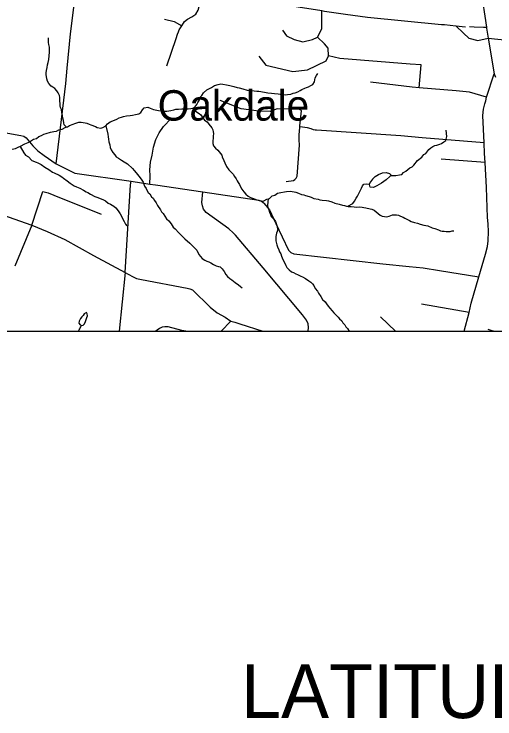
# Model space of a CAD drawing. Extents: x 0 to 69.5, y -4.5 to 22.
# Drawn here: x 2.482 to 3.731, y 13.194 to 15.023 of the extents above; entities that cross this region are included whole.
import ezdxf

# ---------------------------------------------------------------- set-up
doc = ezdxf.new("R2010")
doc.units = 0
for name, color, linetype in [('GM_X_County_Road', 7, 'Continuous'), ('GM_X_County_ROW', 7, 'Continuous'), ('GM_X_Minor_Lake', 7, 'Continuous'), ('GM_X_Minor_River', 7, 'Continuous'), ('GM_X_Township_Subdivision', 7, 'Continuous'), ('GM_X_Unincorporated_Text', 7, 'Continuous'), ('SH_Data', 7, 'Continuous')]:
    doc.layers.add(name, color=color, linetype=linetype)

msp = doc.modelspace()

# ---------------------------------------------------------------- linework, layer by layer
at = {"layer": 'GM_X_County_Road'}
for points in [[(2.2258, 15.2235), (2.2987, 15.186), (2.3184, 15.1766), (2.3423, 15.1693), (2.373, 15.1638), (2.4076, 15.1648), (2.4442, 15.1636), (2.6483, 15.131), (2.7856, 15.1056), (2.9731, 15.0809), (3.1585, 15.0511), (3.281, 15.0319), (3.2884, 15.0308), (3.343, 15.0226), (3.3998, 15.0151), (3.5922, 14.9963), (3.5999, 14.9956)], [(2.6198, 14.8825), (2.6281, 14.9717), (2.6483, 15.131)], [(3.6945, 15.0867), (3.7086, 14.9889), (3.7089, 14.9865), (3.7134, 14.9601), (3.7288, 14.8681), (3.7325, 14.8589)], [(3.5999, 14.9956), (3.6295, 14.9929), (3.6491, 14.9734), (3.6629, 14.9607), (3.686, 14.9547), (3.7134, 14.9601)], [(3.6295, 14.9929), (3.6543, 14.9903)], [(3.6768, 14.9901), (3.7006, 14.9892)], [(3.7134, 14.9601), (3.8399, 14.9472), (3.85, 14.9435), (3.9106, 14.9291), (3.9265, 14.9232), (3.9472, 14.9185), (4.0106, 14.9118), (4.0583, 14.9068)], [(3.7129, 14.4789), (3.7118, 14.495), (3.7085, 14.5729), (3.7053, 14.6379), (3.7039, 14.6616), (3.7029, 14.6892), (3.699, 14.7598), (3.7006, 14.7761), (3.7047, 14.7898), (3.7068, 14.7981), (3.7092, 14.807), (3.7288, 14.8681)], [(2.3393, 14.7315), (2.4266, 14.7207), (2.4996, 14.7079), (2.5073, 14.7062), (2.5134, 14.7016), (2.5301, 14.6807), (2.5431, 14.6681), (2.5604, 14.6558), (2.5911, 14.634), (2.6279, 14.6158), (2.6392, 14.6102), (2.7855, 14.589), (2.8343, 14.5818), (2.8491, 14.5796)], [(2.7703, 14.3525), (2.7846, 14.5795), (2.7846, 14.5795)], [(2.7846, 14.5795), (2.7855, 14.589)], [(2.8491, 14.5796), (2.9723, 14.5615), (3.1178, 14.5405), (3.1238, 14.5388), (3.129, 14.5343)], [(2, 14.5396), (2.019, 14.5376), (2.0727, 14.5308), (2.2375, 14.5181), (2.273, 14.5212), (2.3066, 14.52), (2.3558, 14.5219), (2.3858, 14.5244), (2.3884, 14.5247), (2.3912, 14.5244), (2.4003, 14.5218), (2.4213, 14.5128), (2.5283, 14.475), (2.5681, 14.4589), (2.6134, 14.4384), (2.6877, 14.3965), (2.7703, 14.3525)], [(3.129, 14.5343), (3.1309, 14.5326), (3.1449, 14.5152), (3.1617, 14.4795), (3.1943, 14.4106), (3.2005, 14.404), (3.2088, 14.4008), (3.4396, 14.3745), (3.5082, 14.3678), (3.5441, 14.3643), (3.5868, 14.3576), (3.6892, 14.3408)], [(3.6512, 14.2), (3.6635, 14.249), (3.6693, 14.2725), (3.6892, 14.3408), (3.7063, 14.3997), (3.7111, 14.4197), (3.7131, 14.4349), (3.714, 14.4585), (3.7129, 14.4777), (3.7129, 14.4789)], [(2.7703, 14.3525), (2.7763, 14.3485), (2.7925, 14.34), (2.7996, 14.3369), (2.8125, 14.3338), (2.9315, 14.3114), (2.9387, 14.3101), (2.9454, 14.3072), (2.9907, 14.2625), (3.0097, 14.2478), (3.0297, 14.2365), (3.0449, 14.2264), (3.0549, 14.2233), (3.0685, 14.2188), (3.1275, 14.2)]]:
    msp.add_lwpolyline(points, dxfattribs=at)
at = {"layer": 'GM_X_County_ROW'}
for points in [[(3.6649, 14.9905), (3.6768, 14.9901)], [(3.7006, 14.9892), (3.7086, 14.9889)], [(2.5911, 14.634), (2.6162, 14.8432), (2.6198, 14.8825)]]:
    msp.add_lwpolyline(points, dxfattribs=at)
at = {"layer": 'GM_X_Minor_Lake'}
for points in [[(2.657, 14.2147), (2.6612, 14.2158), (2.665, 14.2195), (2.6674, 14.2248), (2.6691, 14.2308), (2.6711, 14.2357), (2.6723, 14.2402), (2.6717, 14.2448), (2.6702, 14.2483), (2.6641, 14.245), (2.661, 14.2412), (2.6575, 14.2371), (2.6543, 14.233), (2.6508, 14.2259), (2.6499, 14.2206)], [(2.6499, 14.2206), (2.6538, 14.2165), (2.657, 14.2147)]]:
    msp.add_lwpolyline(points, dxfattribs=at)
at = {"layer": 'GM_X_Minor_River'}
for points in [[(2.6176, 14.7296), (2.6118, 14.7354), (2.6108, 14.7411), (2.6098, 14.7472), (2.6088, 14.7526), (2.6075, 14.7598), (2.6062, 14.7679), (2.6049, 14.7751), (2.6027, 14.7802), (2.6017, 14.7848), (2.6011, 14.7897), (2.6006, 14.7981), (2.6004, 14.8065), (2.5994, 14.8119), (2.5965, 14.8184), (2.5925, 14.8239), (2.5873, 14.8297), (2.5829, 14.8336), (2.578, 14.8361), (2.5721, 14.8427), (2.5685, 14.8493), (2.5671, 14.8546), (2.5657, 14.8608), (2.5655, 14.8654), (2.5653, 14.8707), (2.5662, 14.8764), (2.5675, 14.8843), (2.5689, 14.8915), (2.5705, 14.8976), (2.5719, 14.9055), (2.5733, 14.915), (2.5739, 14.9245), (2.5741, 14.9321), (2.5735, 14.9375), (2.5722, 14.944), (2.5716, 14.9493), (2.5714, 14.9562), (2.5711, 14.9615)], [(3.1411, 14.8188), (3.1502, 14.8178), (3.1586, 14.8168), (3.1681, 14.8161), (3.173, 14.8156), (3.1821, 14.8142), (3.1878, 14.8137), (3.1923, 14.8139), (3.2007, 14.8152), (3.2065, 14.8174), (3.2115, 14.8187), (3.2184, 14.8216), (3.2246, 14.8245), (3.2292, 14.827), (3.2369, 14.831), (3.2415, 14.8324), (3.2469, 14.8345), (3.2527, 14.8374), (3.2577, 14.8407), (3.2617, 14.8474), (3.2642, 14.8572), (3.2675, 14.864), (3.271, 14.8685)], [(2.4766, 14.6721), (2.4854, 14.6741), (2.4923, 14.6774), (2.4989, 14.6799), (2.5097, 14.6864), (2.5185, 14.69), (2.5247, 14.6929), (2.5324, 14.698), (2.5397, 14.7004), (2.5463, 14.7052), (2.5532, 14.7077), (2.5594, 14.7113), (2.5652, 14.7134), (2.5763, 14.7162), (2.5851, 14.7186), (2.5916, 14.7192), (2.5981, 14.7224), (2.6065, 14.7245), (2.6147, 14.7288), (2.6208, 14.7305), (2.6254, 14.7338), (2.635, 14.7374), (2.64, 14.7391), (2.6504, 14.7423), (2.6561, 14.7429), (2.6663, 14.7407), (2.6712, 14.7398), (2.6769, 14.737), (2.6814, 14.7353), (2.6934, 14.7312), (2.6979, 14.7288), (2.707, 14.7266), (2.7124, 14.7283), (2.7201, 14.7331), (2.7244, 14.7383), (2.7314, 14.7438), (2.7379, 14.7459), (2.7483, 14.7506), (2.7549, 14.7534), (2.7606, 14.7556), (2.7656, 14.7573), (2.774, 14.7586), (2.7832, 14.7599), (2.7893, 14.7605), (2.797, 14.7622), (2.8061, 14.7638), (2.8112, 14.7675), (2.8155, 14.7742), (2.8195, 14.7798), (2.829, 14.7814), (2.8351, 14.779), (2.8437, 14.7757), (2.857, 14.773), (2.863, 14.7717), (2.8694, 14.7708), (2.8786, 14.7709), (2.8889, 14.7729), (2.8965, 14.7742), (2.9023, 14.776), (2.9088, 14.7766), (2.9179, 14.7771), (2.9285, 14.7768), (2.9343, 14.7774), (2.9408, 14.7779), (2.9457, 14.7786), (2.9515, 14.7818), (2.9566, 14.7882), (2.9594, 14.7934), (2.9622, 14.799), (2.9655, 14.8073), (2.9694, 14.8118), (2.9738, 14.8189), (2.9824, 14.8263), (2.9897, 14.8295), (2.9947, 14.8328), (3.0021, 14.8379), (3.0117, 14.8403), (3.0189, 14.842), (3.0239, 14.8415), (3.0333, 14.8397), (3.0424, 14.8379), (3.0522, 14.835), (3.0616, 14.8328), (3.0662, 14.8316), (3.076, 14.8286), (3.0869, 14.8256), (3.0964, 14.825), (3.1055, 14.824), (3.1124, 14.8234), (3.1173, 14.8233), (3.132, 14.8206), (3.1411, 14.8188)], [(2.946, 14.7767), (2.9505, 14.7739), (2.9557, 14.7691), (2.9624, 14.7648), (2.9669, 14.7616), (2.9706, 14.7562), (2.9764, 14.748), (2.9835, 14.7432), (2.9879, 14.7374), (2.9953, 14.7281), (2.9978, 14.7227), (2.9992, 14.7173), (2.9994, 14.7127), (2.9993, 14.7066), (2.9988, 14.7021), (2.9982, 14.6929), (2.998, 14.6869), (3.0001, 14.6807), (3.0049, 14.6749), (3.0112, 14.6701), (3.0149, 14.6654), (3.0215, 14.6569), (3.0225, 14.6523), (3.0265, 14.6434), (3.029, 14.6373), (3.0337, 14.6276), (3.0395, 14.6191), (3.0506, 14.6073), (3.0542, 14.6011), (3.059, 14.5953), (3.0616, 14.5907), (3.0641, 14.5856), (3.067, 14.581), (3.0702, 14.5744), (3.0731, 14.569), (3.0783, 14.5616), (3.0838, 14.5554), (3.0898, 14.5506), (3.0961, 14.5467), (3.1037, 14.5445), (3.1123, 14.5409), (3.124, 14.5379), (3.1305, 14.5381), (3.1386, 14.5424), (3.1451, 14.5445), (3.1525, 14.5512), (3.1587, 14.5533), (3.166, 14.558), (3.1748, 14.5601), (3.184, 14.5621), (3.1893, 14.5627), (3.1996, 14.5632), (3.214, 14.5609), (3.2204, 14.558), (3.2279, 14.5552), (3.2343, 14.5538), (3.2389, 14.5522), (3.2483, 14.5496), (3.2532, 14.5476), (3.2607, 14.5447), (3.2717, 14.5425), (3.2762, 14.5412), (3.2823, 14.5403), (3.2933, 14.5389), (3.2982, 14.538), (3.3069, 14.5354), (3.3152, 14.5325), (3.3261, 14.53), (3.3344, 14.5267), (3.3401, 14.5261), (3.3454, 14.5245), (3.3499, 14.524), (3.3575, 14.5234), (3.3651, 14.5228), (3.3723, 14.5222), (3.3799, 14.5224), (3.386, 14.5218), (3.3905, 14.5209), (3.3951, 14.5204), (3.4064, 14.5178), (3.4113, 14.5169), (3.417, 14.5145), (3.4222, 14.5101), (3.4274, 14.5054), (3.4322, 14.5015), (3.4374, 14.4983), (3.4435, 14.4974), (3.4496, 14.4972), (3.4561, 14.4985), (3.4649, 14.5017), (3.4699, 14.5023), (3.4748, 14.5022), (3.4801, 14.5013), (3.4854, 14.4989), (3.4922, 14.4964), (3.4966, 14.4936), (3.5015, 14.4904), (3.5086, 14.4875), (3.5131, 14.4848), (3.5214, 14.4819), (3.5294, 14.4801)], [(2.72, 14.733), (2.7256, 14.7116), (2.7266, 14.7047), (2.7272, 14.6986), (2.7281, 14.6917), (2.7302, 14.6837), (2.7315, 14.6764), (2.7336, 14.6703), (2.7384, 14.664), (2.7439, 14.6578), (2.7472, 14.6524), (2.7528, 14.6488), (2.761, 14.6436), (2.7674, 14.6396), (2.776, 14.634), (2.789, 14.6223), (2.7938, 14.6168), (2.7989, 14.6109), (2.8059, 14.6027), (2.8118, 14.595), (2.8169, 14.5864), (2.8205, 14.5768), (2.8248, 14.5706), (2.8266, 14.566), (2.8299, 14.5598), (2.8343, 14.5563), (2.8387, 14.5489), (2.8432, 14.545), (2.8468, 14.5395), (2.8508, 14.533), (2.8545, 14.5264), (2.8617, 14.5147), (2.8643, 14.5101), (2.8691, 14.5058), (2.8779, 14.4918), (2.8834, 14.4863), (2.8897, 14.4786), (2.8952, 14.4704), (2.9004, 14.4661), (2.91, 14.4551), (2.9155, 14.4497), (2.9207, 14.4442), (2.9251, 14.4399), (2.9385, 14.4281), (2.9452, 14.4218), (2.9496, 14.4175), (2.9563, 14.4101), (2.9621, 14.3989), (2.9661, 14.3942), (2.9705, 14.3883), (2.9773, 14.3844), (2.9825, 14.3819), (2.9878, 14.3799), (2.9927, 14.3774), (2.9994, 14.3731), (3.0069, 14.3698), (3.0126, 14.3681), (3.0171, 14.3669), (3.0227, 14.3618), (3.0278, 14.3548), (3.0314, 14.3474), (3.0358, 14.342), (3.0418, 14.3372), (3.0478, 14.3336), (3.0559, 14.3262), (3.0645, 14.3206), (3.0697, 14.3159), (3.0742, 14.3127)], [(3.4608, 14.6044), (3.4733, 14.6045), (3.4832, 14.6059), (3.4887, 14.6069), (3.493, 14.6117), (3.4992, 14.6154), (3.5093, 14.6238), (3.5154, 14.6263), (3.5201, 14.6308), (3.5296, 14.6431), (3.5405, 14.6519), (3.546, 14.6586), (3.551, 14.6615), (3.5589, 14.672), (3.5639, 14.676), (3.5697, 14.6793), (3.5744, 14.6822), (3.5801, 14.6832), (3.5874, 14.6852), (3.592, 14.6874), (3.5982, 14.6914), (3.6029, 14.6951), (3.6054, 14.7057), (3.6044, 14.7221)], [(2.4976, 14.6794), (2.5068, 14.6629), (2.5112, 14.6571), (2.519, 14.6523), (2.5279, 14.6433), (2.5392, 14.6384), (2.5437, 14.6371), (2.552, 14.6327), (2.562, 14.6259), (2.5718, 14.6196), (2.5815, 14.6128), (2.586, 14.6112), (2.5987, 14.6047), (2.6055, 14.6007), (2.6103, 14.5975), (2.6193, 14.5901), (2.6278, 14.5841), (2.6376, 14.5777), (2.6436, 14.5745), (2.6522, 14.5712), (2.662, 14.566), (2.6691, 14.562), (2.6736, 14.5596), (2.6799, 14.5556), (2.6919, 14.5492), (2.6965, 14.5479), (2.7036, 14.5451), (2.7138, 14.5413), (2.7194, 14.5385), (2.7261, 14.5326), (2.7325, 14.5294), (2.7411, 14.5246), (2.7463, 14.5203), (2.7522, 14.5125), (2.7573, 14.5047), (2.7605, 14.4985), (2.763, 14.4928), (2.7678, 14.4846), (2.7714, 14.4781), (2.7749, 14.4732)], [(3.4125, 14.5946), (3.4195, 14.6015), (3.4283, 14.6063), (3.4383, 14.6106), (3.4485, 14.6119), (3.4572, 14.6094), (3.4609, 14.6048), (3.4574, 14.6014), (3.4481, 14.5929), (3.4362, 14.5844), (3.4242, 14.5771), (3.415, 14.5731), (3.4067, 14.5741), (3.4046, 14.5806), (3.4044, 14.5819)], [(3.3486, 14.5241), (3.3615, 14.5313), (3.3659, 14.5376), (3.3706, 14.5451), (3.3738, 14.5507), (3.3803, 14.5642), (3.3843, 14.571), (3.3871, 14.577), (3.3899, 14.5819), (3.3976, 14.5826), (3.4044, 14.5816)], [(3.4125, 14.5946), (3.4071, 14.5873), (3.4044, 14.5819)], [(3.1416, 14.5434), (3.1404, 14.5268), (3.141, 14.5199), (3.1432, 14.5153), (3.1449, 14.5087), (3.1478, 14.503), (3.1499, 14.4979), (3.1562, 14.4905), (3.1606, 14.4847), (3.1627, 14.4793), (3.1645, 14.4747), (3.1655, 14.4701), (3.1665, 14.4647), (3.1652, 14.4587), (3.1636, 14.4542), (3.1618, 14.4462), (3.1613, 14.4409), (3.1619, 14.4344), (3.1639, 14.4244), (3.1657, 14.4187), (3.1693, 14.4114), (3.171, 14.4056), (3.1743, 14.4009), (3.1768, 14.3944), (3.18, 14.3863), (3.1836, 14.3801), (3.1872, 14.3709), (3.1905, 14.3651), (3.1964, 14.3596), (3.2027, 14.3537), (3.2076, 14.3524), (3.2132, 14.3488), (3.2177, 14.3472), (3.2264, 14.3427), (3.2309, 14.3415), (3.2391, 14.3371), (3.2473, 14.3304), (3.2522, 14.3276), (3.2566, 14.3232), (3.2603, 14.3186), (3.2639, 14.3112), (3.2698, 14.3042), (3.2727, 14.2988), (3.2789, 14.2903), (3.2829, 14.2825), (3.2896, 14.2763), (3.2929, 14.2712), (3.298, 14.265), (3.3017, 14.2595), (3.308, 14.2533), (3.3124, 14.2478), (3.3172, 14.2427), (3.3239, 14.2368), (3.3272, 14.2322), (3.3331, 14.2267), (3.3357, 14.222), (3.3408, 14.2162), (3.3437, 14.2112), (3.3482, 14.2072), (3.3522, 14.2003), (3.3525, 14.2)], [(3.5294, 14.4801), (3.5361, 14.4776), (3.546, 14.4755), (3.5562, 14.4737), (3.5675, 14.4684), (3.575, 14.4667), (3.5844, 14.463), (3.5889, 14.4609), (3.5935, 14.46), (3.5988, 14.4595), (3.6037, 14.459), (3.609, 14.4589), (3.6147, 14.4591), (3.6193, 14.4605), (3.6238, 14.4601)], [(2.6489, 14.2), (2.6506, 14.2035), (2.6522, 14.2065), (2.6531, 14.2087), (2.655, 14.2114), (2.657, 14.2147)]]:
    msp.add_lwpolyline(points, dxfattribs=at)
at = {"layer": 'GM_X_Township_Subdivision'}
for points in [[(2.8788, 14.8884), (2.903, 14.9595), (2.906, 14.9705), (2.9086, 14.9773), (2.9106, 14.9824), (2.9175, 14.9927), (2.9243, 15.0038), (2.9323, 15.0098), (2.9433, 15.0159), (2.9542, 15.0232), (2.96, 15.0328), (2.9638, 15.0458), (2.9731, 15.0809)], [(3.1791, 14.9817), (3.1891, 14.9662), (3.2089, 14.9569), (3.2321, 14.9514), (3.2569, 14.9574), (3.2696, 14.9635), (3.2812, 14.9844), (3.2812, 15.0159), (3.281, 15.0319)], [(2.8724, 15.0102), (2.8973, 15.0035), (2.9175, 14.9927)], [(3.1174, 14.9138), (3.1361, 14.8907), (3.2056, 14.8736), (3.2442, 14.878), (3.2922, 14.9017), (3.2983, 14.9149), (3.2977, 14.9343), (3.2878, 14.9458), (3.2696, 14.9635)], [(3.5104, 14.8933), (3.3275, 14.9078), (3.2983, 14.9149)], [(3.5395, 14.891), (3.5104, 14.8933)], [(3.534, 14.8318), (3.5395, 14.891)], [(3.7092, 14.807), (3.6647, 14.8203), (3.6296, 14.8239), (3.534, 14.8318), (3.5161, 14.8334), (3.4079, 14.8466)], [(3.2244, 14.733), (3.228, 14.7716), (3.2278, 14.7727), (3.2271, 14.7736), (3.225, 14.7749), (3.2209, 14.7761), (3.1654, 14.777), (3.1471, 14.7699), (3.1179, 14.771), (3.0716, 14.7771), (3.0175, 14.7986)], [(2.8343, 14.5818), (2.8356, 14.603), (2.8348, 14.6186), (2.8364, 14.6383), (2.8403, 14.6568), (2.8439, 14.6776), (2.8497, 14.6976), (2.8585, 14.7149), (2.8703, 14.7309), (2.8902, 14.7524)], [(3.1888, 14.5889), (3.2075, 14.5915), (3.211, 14.594), (3.2141, 14.5974), (3.2169, 14.6022), (3.2227, 14.6826), (3.2219, 14.6967), (3.2223, 14.7111), (3.2229, 14.7176), (3.2241, 14.7304), (3.2244, 14.733)], [(3.2639, 14.7218), (3.2635, 14.7219), (3.2594, 14.7223), (3.253, 14.7252), (3.2439, 14.7277), (3.2241, 14.7304)], [(3.7029, 14.6892), (3.5414, 14.7019), (3.4859, 14.707), (3.2677, 14.7214), (3.2639, 14.7218)], [(3.7053, 14.6379), (3.5914, 14.6467)], [(2.5283, 14.475), (2.5569, 14.5629), (2.5701, 14.5592), (2.5853, 14.5531), (2.6001, 14.5473), (2.6241, 14.5371), (2.7084, 14.5037)], [(3.2459, 14.2), (3.2461, 14.2096), (3.2452, 14.2195), (3.2409, 14.2291), (3.231, 14.2426), (3.1286, 14.3648), (3.0571, 14.4494), (3.0512, 14.4552), (3.0393, 14.4658), (2.9808, 14.5078), (2.9742, 14.5164), (2.971, 14.5252), (2.9697, 14.5339), (2.9723, 14.5615)], [(2.5283, 14.475), (2.4837, 14.3691)], [(2.7703, 14.3525), (2.7545, 14.2)], [(3.6635, 14.249), (3.5396, 14.27)], [(3.4723, 14.2), (3.4339, 14.2376)], [(3.0449, 14.2264), (3.0201, 14.2)], [(2.9282, 14.2), (2.9179, 14.2021), (2.8823, 14.2115), (2.8735, 14.2115), (2.8665, 14.2103), (2.8591, 14.2069), (2.8536, 14.2031), (2.8501, 14.2)], [(3.7266, 14.2), (3.7238, 14.2009), (3.713, 14.2047)]]:
    msp.add_lwpolyline(points, dxfattribs=at)
at = {"layer": 'SH_Data'}
msp.add_line((2, 14.2), (8.8, 14.2), dxfattribs=at)

# ---------------------------------------------------------------- texts
at = {"layer": 'GM_X_Unincorporated_Text'}
msp.add_text('Oakdale', height=0.07898, rotation=0, dxfattribs=at).set_placement((2.855, 14.7465))
at = {"layer": 'SH_Data'}
msp.add_text('LATITUDE:  39° 16\' 12"     LONGITUDE:  -84° 34\' 26"', height=0.14, dxfattribs=at).set_placement((3.071, 13.1959))

doc.saveas('drawing.dxf')
